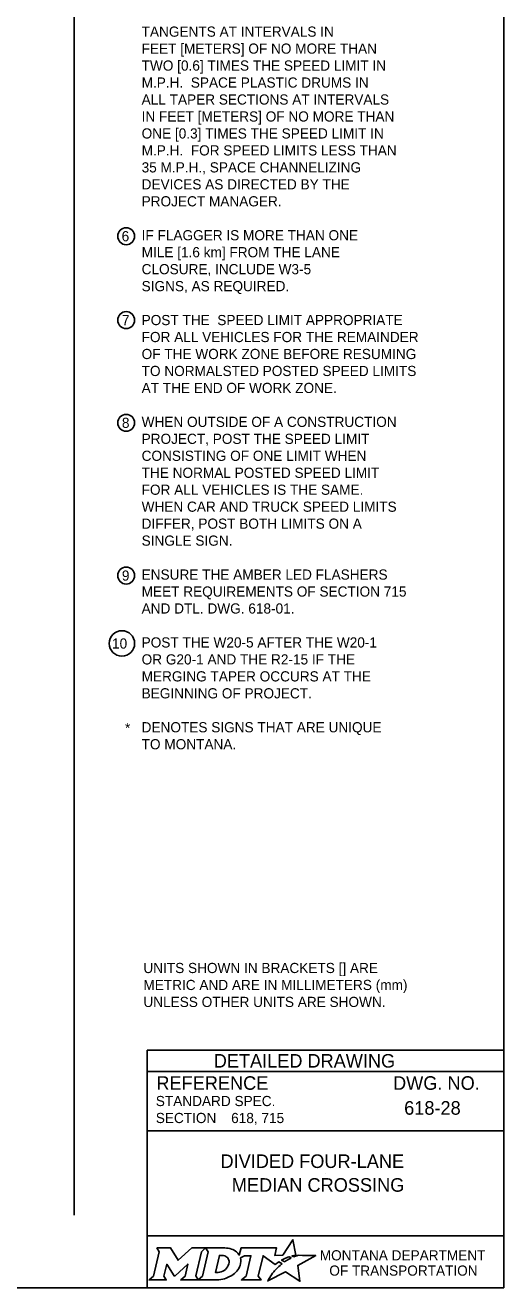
# Model space of a CAD drawing. Extents: x 49991.4 to 50021, y 49987.6 to 50011.4.
# Drawn here: x 50013.93 to 50016.75, y 49987.8 to 49995.24 of the extents above; entities that cross this region are included whole.
import ezdxf

# ---------------------------------------------------------------- set-up
doc = ezdxf.new("R2010")
doc.units = 0
for name, color, linetype in [('Default', 7, 'Continuous'), ('Level 1', 7, 'Continuous'), ('Level 2', 7, 'Continuous'), ('Level 3', 7, 'Continuous'), ('Level 5', 7, 'Continuous')]:
    doc.layers.add(name, color=color, linetype=linetype)

msp = doc.modelspace()

# ---------------------------------------------------------------- linework, layer by layer
at = {"layer": 'Default'}
for points in [[(50015.5126, 49987.9811), (50015.5023, 49987.9867), (50015.5139, 49987.9895), (50015.5255, 49987.9915), (50015.5081, 49988.0816), (50015.4486, 49987.9903), (50015.4013, 49987.9896), (50015.4116, 49988.0337), (50015.2024, 49988.0338), (50015.1923, 49987.9913), (50015.1865, 49987.9996)], [(50014.7056, 49988.0338), (50014.7197, 49988.0104), (50014.6862, 49987.8671), (50014.6605, 49987.8446), (50014.7621, 49987.8446), (50014.7486, 49987.8674), (50014.7648, 49987.9375), (50014.8085, 49987.8685), (50014.8138, 49987.8685), (50014.8889, 49987.938), (50014.8725, 49987.8669), (50014.8478, 49987.8449), (50014.9494, 49987.8449), (50014.9356, 49987.8682), (50014.9688, 49988.0106)], [(50014.9688, 49988.0106), (50014.9941, 49988.0338), (50014.9117, 49988.0338), (50014.8321, 49987.9608), (50014.7876, 49988.0335), (50014.7056, 49988.0338)], [(50015.1077, 49988.0338), (50014.9941, 49988.0338), (50015.0088, 49988.0109), (50014.9749, 49987.8671), (50014.9494, 49987.8449), (50015.06, 49987.8449)], [(50015.1317, 49987.9471), (50015.1305, 49987.939), (50015.1273, 49987.9297), (50015.1231, 49987.9215), (50015.1175, 49987.914), (50015.111, 49987.9071), (50015.1031, 49987.9008), (50015.0948, 49987.8961), (50015.0857, 49987.8922), (50015.0766, 49987.8899), (50015.0674, 49987.889), (50015.0515, 49987.889), (50015.0751, 49987.989), (50015.0911, 49987.989), (50015.0987, 49987.9884), (50015.1063, 49987.9865), (50015.1129, 49987.9835), (50015.119, 49987.9793), (50015.1238, 49987.9743), (50015.1275, 49987.9683), (50015.1302, 49987.9621), (50015.1318, 49987.9547), (50015.1318, 49987.9517), (50015.1317, 49987.9471)], [(50015.1991, 49987.9747), (50015.2237, 49987.9878), (50015.2606, 49987.9878), (50015.232, 49987.8673), (50015.2045, 49987.8446), (50015.3207, 49987.8446), (50015.3037, 49987.8675), (50015.3319, 49987.9877), (50015.4032, 49987.936), (50015.4243, 49987.9511), (50015.444, 49987.9402)], [(50015.3882, 49987.8843), (50015.3729, 49987.8599), (50015.3682, 49987.8524), (50015.3624, 49987.8438), (50015.3601, 49987.8395), (50015.4654, 49987.8926), (50015.5493, 49987.8375), (50015.5362, 49987.9302), (50015.6431, 49987.9886), (50015.5938, 49987.9894), (50015.5637, 49987.9898), (50015.5429, 49987.9901), (50015.5361, 49987.9886), (50015.5312, 49987.9874), (50015.5228, 49987.9851), (50015.5126, 49987.9811)], [(50015.4622, 49987.9535), (50015.4598, 49987.9518), (50015.4415, 49987.9614), (50015.4518, 49987.9671), (50015.4559, 49987.9693), (50015.4645, 49987.9733), (50015.4702, 49987.9759), (50015.4781, 49987.9789), (50015.4854, 49987.9816), (50015.4972, 49987.9742), (50015.4932, 49987.9721), (50015.4886, 49987.9696), (50015.4844, 49987.9674), (50015.4794, 49987.9645), (50015.4775, 49987.9634), (50015.4748, 49987.9618), (50015.4723, 49987.9604), (50015.47, 49987.9588), (50015.4674, 49987.957), (50015.4647, 49987.9552), (50015.4622, 49987.9535)], [(50015.1057, 49987.8522), (50015.1141, 49987.8548), (50015.1271, 49987.8602), (50015.1475, 49987.8712)], [(50015.4021, 49987.9004), (50015.4021, 49987.9004)]]:
    msp.add_lwpolyline(points, dxfattribs=at)
for centre, radius, start, end in [((50015.0868, 49987.9727), 0.1183, 300.91025, 339.13831), ((50015.1308, 49987.9554), 0.0709, 339.53292, 15.85821)]:
    msp.add_arc(centre, radius, start, end, dxfattribs=at)
for centre, major_axis, ratio, start_param, end_param in [((50015.1056, 49987.9864), (0.0834, -0.0037), 0.568097, 0.61298, 1.570796), ((50015.1612, 49987.9937), (0.0361, -0.0295), 0.469099, 1.225588, 1.570796), ((50015.4329, 49987.9305), (-0.0112, -0.0097), 0.021651, 3.157348, 6.283185), ((50015.3952, 49987.8923), (-0.00694, -0.00806), 0.008222, 0, 3.137361), ((50015.4119, 49987.9106), (-0.0098, -0.0102), 0.016458, 3.141593, 6.279097), ((50015.0603, 49987.9932), (0, 0.1484), 0.987302, 3.139398, 3.456847)]:
    msp.add_ellipse(centre, major_axis=major_axis, ratio=ratio, start_param=start_param, end_param=end_param, dxfattribs=at)
at = {"layer": 'Level 1'}
msp.add_lwpolyline([(49999.3835, 49998.9992), (50016.7501, 49998.9992), (50016.7501, 49987.7988), (49999.3835, 49987.7988)], close=True, dxfattribs=at)
at = {"layer": 'Level 2'}
for centre, radius in [((50014.5258, 49993.9967), 0.05), ((50014.5258, 49993.502), 0.05), ((50014.5258, 49992.8967), 0.05), ((50014.5258, 49991.9964), 0.05), ((50014.5008, 49991.5964), 0.075)]:
    msp.add_circle(centre, radius, dxfattribs=at)
at = {"layer": 'Level 3'}
msp.add_line((50014.2203, 49998.9992), (50014.2203, 49988.2257), dxfattribs=at)
at = {"layer": 'Level 5'}
for p, q in [((50016.7501, 49989.1988), (50014.6501, 49989.1988)), ((50014.6501, 49989.1988), (50014.6501, 49987.7988)), ((50016.7501, 49989.0738), (50014.6501, 49989.0738)), ((50016.3862, 49988.8587), (50016.3862, 49988.8587)), ((50015.1444, 49988.7993), (50015.1444, 49988.7993)), ((50016.7501, 49988.7238), (50014.6501, 49988.7238)), ((50015.7001, 49988.4747), (50015.7001, 49988.4747)), ((50016.7501, 49988.1057), (50014.6501, 49988.1057))]:
    msp.add_line(p, q, dxfattribs=at)

# ---------------------------------------------------------------- texts
at = {"layer": 'Default'}
for s, p in [('MONTANA DEPARTMENT', (50015.6663, 49987.96)), ('OF TRANSPORTATION', (50015.7225, 49987.87))]:
    msp.add_text(s, height=0.06, dxfattribs=at).set_placement(p)
at = {"layer": 'Level 2'}
for s, height, p in [('TANGENTS AT INTERVALS IN', 0.06, (50014.6169, 49995.1724)), ('FEET [METERS] OF NO MORE THAN', 0.06, (50014.6169, 49995.0724)), ('TWO [0.6] TIMES THE SPEED LIMIT IN', 0.06, (50014.6169, 49994.9724)), ('M.P.H.  SPACE PLASTIC DRUMS IN', 0.06, (50014.6169, 49994.8724)), ('ALL TAPER SECTIONS AT INTERVALS', 0.06, (50014.6169, 49994.7724)), ('IN FEET [METERS] OF NO MORE THAN', 0.06, (50014.6169, 49994.6724)), ('ONE [0.3] TIMES THE SPEED LIMIT IN', 0.06, (50014.6169, 49994.5724)), ('M.P.H.  FOR SPEED LIMITS LESS THAN', 0.06, (50014.6169, 49994.4724)), ('35 M.P.H., SPACE CHANNELIZING', 0.06, (50014.6169, 49994.3724)), ('DEVICES AS DIRECTED BY THE', 0.06, (50014.6169, 49994.2724)), ('PROJECT MANAGER.', 0.06, (50014.6169, 49994.1724)), ('IF FLAGGER IS MORE THAN ONE', 0.06, (50014.6169, 49993.9724)), ('6', 0.06, (50014.4992, 49993.9667)), ('MILE [1.6 km] FROM THE LANE', 0.06, (50014.6169, 49993.8724)), ('CLOSURE, INCLUDE W3-5', 0.06, (50014.6169, 49993.7724)), ('SIGNS, AS REQUIRED.', 0.06, (50014.6169, 49993.6724)), ('7', 0.06, (50014.5008, 49993.472)), ('POST THE  SPEED LIMIT APPROPRIATE', 0.06, (50014.6169, 49993.4724)), ('FOR ALL VEHICLES FOR THE REMAINDER', 0.06, (50014.6169, 49993.3724)), ('OF THE WORK ZONE BEFORE RESUMING ', 0.06, (50014.6169, 49993.2724)), ('TO NORMALSTED POSTED SPEED LIMITS ', 0.06, (50014.6169, 49993.1724)), ('AT THE END OF WORK ZONE.', 0.06, (50014.6169, 49993.0724)), ('8', 0.06, (50014.5008, 49992.8667)), ('WHEN OUTSIDE OF A CONSTRUCTION', 0.06, (50014.6169, 49992.8724)), ('PROJECT, POST THE SPEED LIMIT', 0.06, (50014.6169, 49992.7724)), ('CONSISTING OF ONE LIMIT WHEN', 0.06, (50014.6169, 49992.6724)), ('THE NORMAL POSTED SPEED LIMIT', 0.06, (50014.6169, 49992.5724)), ('FOR ALL VEHICLES IS THE SAME.  ', 0.06, (50014.6169, 49992.4724)), ('WHEN CAR AND TRUCK SPEED LIMITS', 0.06, (50014.6169, 49992.3724)), ('DIFFER, POST BOTH LIMITS ON A', 0.06, (50014.6169, 49992.2724)), ('SINGLE SIGN.', 0.06, (50014.6169, 49992.1724)), ('9', 0.06, (50014.5006, 49991.9664)), ('ENSURE THE AMBER LED FLASHERS ', 0.06, (50014.6169, 49991.9724)), ('MEET REQUIREMENTS OF SECTION 715 ', 0.06, (50014.6169, 49991.8724)), ('AND DTL. DWG. 618-01.', 0.06, (50014.6169, 49991.7724)), ('10', 0.06, (50014.4426, 49991.566)), ('POST THE W20-5 AFTER THE W20-1 ', 0.06, (50014.6169, 49991.5724)), ('OR G20-1 AND THE R2-15 IF THE', 0.06, (50014.6169, 49991.4724)), ('MERGING TAPER OCCURS AT THE ', 0.06, (50014.6169, 49991.3724)), ('BEGINNING OF PROJECT.', 0.06, (50014.6169, 49991.2724)), ('DENOTES SIGNS THAT ARE UNIQUE', 0.06, (50014.6169, 49991.0724)), ('*', 0.06, (50014.519, 49991.068)), ('TO MONTANA.', 0.06, (50014.6169, 49990.9724)), ('UNITS SHOWN IN BRACKETS [] ARE ', 0.06, (50014.6273, 49989.6535)), ('METRIC AND ARE IN MILLIMETERS (mm) ', 0.06, (50014.6273, 49989.5535)), ('UNLESS OTHER UNITS ARE SHOWN.', 0.06, (50014.6273, 49989.4535)), ('618-28', 0.08, (50016.1635, 49988.8187)), ('618, 715', 0.06, (50015.1443, 49988.7693)), ('DIVIDED FOUR-LANE', 0.08, (50015.0814, 49988.5047)), ('MEDIAN CROSSING', 0.08, (50015.1482, 49988.3647))]:
    msp.add_text(s, height=height, dxfattribs=at).set_placement(p)
at = {"layer": 'Level 5'}
for s, height, p in [('DETAILED DRAWING', 0.0799, (50015.0418, 49989.0963)), ('REFERENCE', 0.08, (50014.7037, 49988.9654)), ('DWG. NO.', 0.08, (50016.0979, 49988.9654)), ('STANDARD SPEC.', 0.06, (50014.7004, 49988.8694)), ('SECTION', 0.06, (50014.7004, 49988.7694))]:
    msp.add_text(s, height=height, dxfattribs=at).set_placement(p)

doc.saveas('drawing.dxf')
